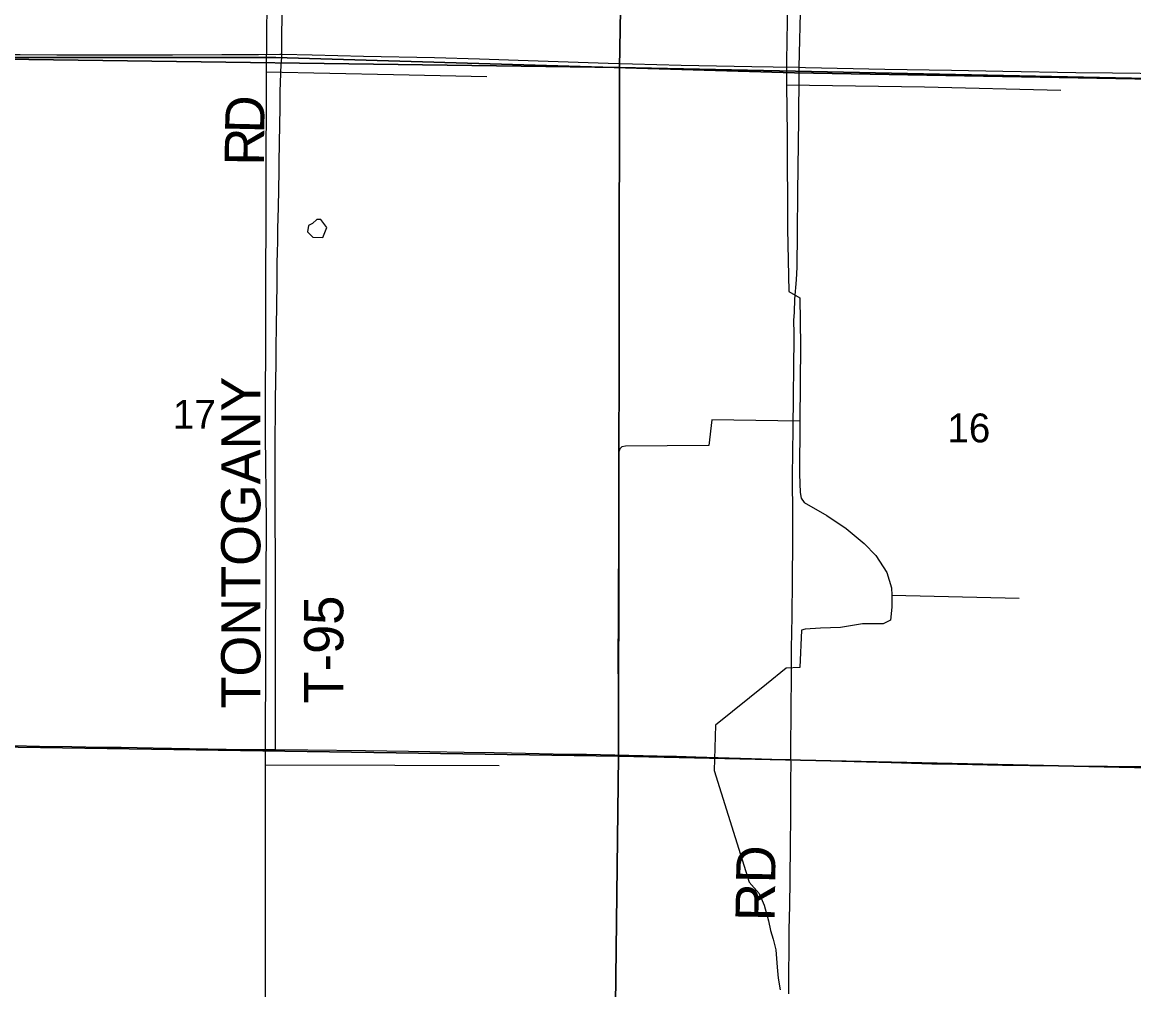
# Model space of a CAD drawing. Extents: x 1443599 to 1910620, y 1028088 to 1361369.
# Drawn here: x 1626749 to 1635252, y 1234297 to 1241703 of the extents above; entities that cross this region are included whole.
import ezdxf

# ---------------------------------------------------------------- set-up
doc = ezdxf.new("R2010")
doc.units = 0
for name, color, linetype in [('GM_X_County_Road', 7, 'Continuous'), ('GM_X_Minor_Lake', 7, 'Continuous'), ('GM_X_Minor_River', 7, 'Continuous'), ('GM_X_Section', 7, 'Continuous'), ('GM_X_Section_Text', 7, 'Continuous'), ('GM_X_Township', 7, 'Continuous'), ('GM_X_Township_Road', 7, 'Continuous'), ('GM_X_Township_Road_Text', 7, 'Continuous')]:
    doc.layers.add(name, color=color, linetype=linetype)

msp = doc.modelspace()

# ---------------------------------------------------------------- linework, layer by layer
at = {"layer": 'GM_X_County_Road'}
for points in [[(1626037.2, 1236177), (1626258.7, 1236174.2), (1626471.8, 1236168.4), (1626685.2, 1236165.4), (1626882, 1236160.5), (1627128.2, 1236159.1), (1627341.4, 1236154.7), (1627505.5, 1236152.6), (1627751.6, 1236148), (1628309.4, 1236138.6), (1628489.9, 1236137), (1628686.8, 1236136.1), (1628687.6, 1236136.1)], [(1628687.6, 1236136.1), (1628932.9, 1236132.6), (1629376, 1236127.4), (1629868.3, 1236120), (1630130.8, 1236115.7), (1630360.4, 1236111.8), (1630491.8, 1236109.7), (1630918.2, 1236101.1), (1631065.9, 1236100.8), (1631607.3, 1236088.4), (1631755, 1236085), (1631902.6, 1236080.5), (1632329.1, 1236067.6), (1632558.7, 1236060.6), (1632630, 1236058.6)], [(1632630, 1236058.6), (1632755.4, 1236054.5), (1633018, 1236047.5), (1633395.2, 1236036), (1633706.8, 1236026.5), (1633903.7, 1236023.2), (1634248.2, 1236016.1), (1634457.5, 1236013.4), (1634740.3, 1236009.9), (1635052.1, 1236007.6), (1635314.6, 1236004.7), (1635478.7, 1236003.7), (1635626.4, 1236002.7), (1635888.9, 1236000.7), (1636036.5, 1235999.5), (1636282.6, 1235997.2), (1636479.5, 1235994.7), (1636594.2, 1235991.8), (1636666.7, 1235993.1)]]:
    msp.add_lwpolyline(points, dxfattribs=at)
at = {"layer": 'GM_X_Minor_Lake'}
msp.add_line((1629002.2, 1240192.4), (1628969.6, 1240160.9), dxfattribs=at)
msp.add_lwpolyline([(1628969.6, 1240160.9), (1628939.2, 1240145.4), (1628930.3, 1240097.4), (1628971.6, 1240058.5), (1629047.7, 1240055.1), (1629079.2, 1240130.8), (1629034.3, 1240193.8), (1629002.2, 1240192.4)], dxfattribs=at)
at = {"layer": 'GM_X_Minor_River'}
for points in [[(1628622.4, 1242132.2), (1628615, 1241323.5), (1628610.9, 1239521.4), (1628608.3, 1238540), (1628615.7, 1237875.6), (1628610.8, 1236986.6), (1628606.5, 1236017.3), (1628607.8, 1234925.5), (1628607.9, 1233982.3)], [(1632606.4, 1242019.5), (1632596.7, 1241403.6), (1632595.3, 1241223), (1632600.1, 1240843.6), (1632602.4, 1240121), (1632613.4, 1239641.2), (1632696.6, 1239593.5), (1632701.7, 1239228.1), (1632696.7, 1238648.2), (1632695, 1238242.8), (1632700.4, 1238104.2), (1632707.5, 1238059.9), (1632731, 1238027.4), (1632905.3, 1237925.8), (1633051.6, 1237826.7), (1633189.7, 1237713.8), (1633280.1, 1237621.8), (1633363.8, 1237491.8), (1633399.6, 1237372.7), (1633402.5, 1237316.4), (1633400.8, 1237224.1), (1633390.9, 1237126), (1633336.3, 1237098.9), (1633178, 1237097.8), (1633009.2, 1237070.9), (1632856.9, 1237065.7), (1632738.6, 1237057.9), (1632710.4, 1237048.4), (1632696.9, 1236763.7), (1632592.7, 1236759.6), (1632442.1, 1236636), (1632051.6, 1236322.2), (1632043, 1235975.1), (1632309.2, 1235119.2), (1632385.7, 1235033.5), (1632424, 1234944.5), (1632457.8, 1234825.4), (1632474.4, 1234750.9), (1632493.2, 1234684.3), (1632513.7, 1234603.6), (1632525.2, 1234468.9), (1632531.6, 1234384.5), (1632545.9, 1234295.9)], [(1628615, 1241323.5), (1629588.2, 1241303.3), (1630303, 1241287.9)], [(1632595.3, 1241223), (1633650.7, 1241209.2), (1634693.8, 1241181.7)], [(1632696.7, 1238648.2), (1632023.8, 1238658.8), (1632002.1, 1238462.5), (1631365, 1238458.4), (1631334.8, 1238452.9), (1631320.5, 1238437.1), (1631309.9, 1238407.2), (1631312.4, 1238324.9), (1631305.9, 1236715.4)], [(1633402.5, 1237316.4), (1634375.6, 1237294.2)], [(1628606.5, 1236017.3), (1629600, 1236014.8), (1630397.2, 1236013.9)]]:
    msp.add_lwpolyline(points, dxfattribs=at)
at = {"layer": 'GM_X_Section'}
for points in [[(1626109.6, 1246727.6), (1631408.8, 1246654.1), (1631319.3, 1241355.1), (1626044.2, 1241426.2)], [(1631408.8, 1246654.1), (1636807.6, 1246539.3), (1636704.1, 1241244.4), (1631319.3, 1241355.1)], [(1626044.2, 1241426.2), (1631319.3, 1241355.1), (1631310.2, 1236085), (1626033.2, 1236164.2)], [(1631319.3, 1241355.1), (1636704.1, 1241244.4), (1636650.8, 1235966.8), (1631310.2, 1236085)], [(1626033.2, 1236164.2), (1631310.2, 1236085), (1631247.2, 1230796.7), (1626003.9, 1230849.2)], [(1631310.2, 1236085), (1636650.8, 1235966.8), (1636595.3, 1230648.8), (1631247.2, 1230796.7)]]:
    msp.add_lwpolyline(points, close=True, dxfattribs=at)
at = {"layer": 'GM_X_Township'}
for points in [[(1636706.1, 1241244.3), (1632655.7, 1241314.7), (1628687.8, 1241432.1), (1626059.6, 1241433.1), (1620678.1, 1241550.1), (1620639.2, 1236302.8), (1615310.1, 1236311.4)], [(1636476.6, 1220085.9), (1631101.7, 1220199.8), (1625906.6, 1220301), (1625693.5, 1220295.5), (1620438.7, 1220361.2), (1620464.9, 1220696.8), (1620510.4, 1225659.3), (1620565.2, 1230923), (1620593.8, 1233582.6), (1620639.2, 1236302.8), (1620678.1, 1241550.1), (1626059.6, 1241433.1), (1628687.8, 1241432.1), (1632655.7, 1241314.7), (1636706.1, 1241244.3)]]:
    msp.add_lwpolyline(points, dxfattribs=at)
at = {"layer": 'GM_X_Township_Road'}
for points in [[(1632693.3, 1241357.3), (1632705.5, 1241880.4), (1632713.9, 1242241.5), (1632721, 1242536.9), (1632725.9, 1242783.1), (1632744.7, 1243570.9), (1632752.4, 1243882.8), (1632751.3, 1243948.4), (1632747.7, 1243997.5), (1632741.1, 1244062.8), (1632738.4, 1244111.9), (1632738.1, 1244177.6), (1632752.2, 1244686.3), (1632762.3, 1245014.5), (1632775.3, 1245474), (1632800.7, 1246425.9), (1632804.9, 1246660.3)], [(1628735, 1241457.2), (1628735, 1241457.3), (1628735.1, 1241468.1), (1628735.5, 1241494.6), (1628735.5, 1241517.2), (1628735.8, 1241589.3), (1628738.4, 1241760)], [(1626069.5, 1241459.9), (1626339.6, 1241456.5), (1626503.7, 1241455.6), (1626733.6, 1241454.7), (1627012.7, 1241452.1), (1627505.2, 1241453), (1627899.2, 1241453.4), (1628276.8, 1241455.1), (1628457.4, 1241455.2), (1628555.9, 1241455.7), (1628720, 1241457.5), (1628735, 1241457.2)], [(1628686.1, 1236722.1), (1628686, 1236736.6), (1628686.2, 1236854.8), (1628685.9, 1236940.1), (1628685.6, 1237028.7), (1628685.6, 1237274.9), (1628685.5, 1237406.2), (1628685.7, 1237547.4), (1628685.9, 1237645.8), (1628685.1, 1237862.5), (1628685, 1238033.2), (1628684.5, 1238266.2), (1628685, 1238519), (1628686, 1238712.6), (1628687, 1238821), (1628689, 1238949), (1628691.3, 1239099.9), (1628692.6, 1239214.8), (1628694.6, 1239372.4), (1628698.3, 1239703.9), (1628700.3, 1239868), (1628701.8, 1239933.6), (1628703.4, 1240035.3), (1628705, 1240120.7), (1628708.9, 1240288), (1628713.5, 1240558.9), (1628714.4, 1240637.7), (1628716.3, 1240772.3), (1628719, 1240923.3), (1628721.4, 1241041.4), (1628723.3, 1241172.7), (1628726.7, 1241310.6), (1628729.9, 1241383), (1628732.1, 1241407.3), (1628733.8, 1241429.9), (1628734.7, 1241442.5), (1628735, 1241457.2)], [(1628735, 1241457.2), (1628966.3, 1241453.3), (1629360.1, 1241442.5), (1629901.8, 1241431.5), (1630246.4, 1241421.4), (1630541.8, 1241411.6), (1630771.5, 1241403.8), (1631230.9, 1241388.5), (1631789, 1241374.8), (1632330.6, 1241364.3), (1632494.7, 1241360.1), (1632693.3, 1241357.3)], [(1632630, 1236058.6), (1632629.1, 1236136.8), (1632630.6, 1236432.3), (1632633.6, 1236711.4), (1632634.5, 1236908.4), (1632638, 1237154.6), (1632642, 1237433.6), (1632643.6, 1237729.1), (1632644.9, 1237926), (1632642.1, 1238221.5), (1632643.6, 1238418.5), (1632646.5, 1238582.5), (1632649.6, 1238845.2), (1632652.2, 1239058.6), (1632652, 1239140.4), (1632653.8, 1239205.7), (1632653.3, 1239320.4), (1632652.9, 1239418.9), (1632655.7, 1239484.4), (1632660.3, 1239582.8), (1632672.4, 1239730.1), (1632676.7, 1239828.4), (1632680.4, 1240091.1), (1632682.8, 1240403), (1632689.6, 1240961.2), (1632692.1, 1241305.9), (1632693.3, 1241357.3)], [(1632693.3, 1241357.3), (1632741, 1241356.6), (1633348.3, 1241344.3), (1633857.1, 1241334.4), (1634251.1, 1241328.2), (1634809.2, 1241318.6), (1635088.3, 1241314.4), (1635301.7, 1241311.9), (1635547.9, 1241310), (1636122.5, 1241306.2), (1636516.5, 1241300.3), (1636697, 1241295.6), (1636731.1, 1241294.7)], [(1628687.6, 1236136.1), (1628687.4, 1236159), (1628687.1, 1236195), (1628685.9, 1236263.9), (1628685.2, 1236352.6), (1628685.3, 1236460.9), (1628686.3, 1236634.9), (1628686.1, 1236722.1)], [(1632613.8, 1234266.7), (1632614.2, 1234463.7), (1632615.6, 1234562.2), (1632617, 1234759.2), (1632620.7, 1234939.8), (1632623.5, 1235136.1), (1632627.2, 1235414.9), (1632629.5, 1235611.9), (1632628.5, 1235710.3), (1632629.6, 1235890.9), (1632630.2, 1236038.4), (1632630, 1236058.6)]]:
    msp.add_lwpolyline(points, dxfattribs=at)

# ---------------------------------------------------------------- texts
at = {"layer": 'GM_X_Section_Text'}
for s, p in [('17', (1627901.3, 1238590.8)), ('16', (1633825.9, 1238486.8))]:
    msp.add_text(s, height=221, rotation=0.00001, dxfattribs=at).set_placement(p)
at = {"layer": 'GM_X_Township_Road_Text'}
for s, rotation, p in [('D', 88.73222, (1628599.8, 1240849.5)), ('R', 89.41452, (1628597.3, 1240604.1)), ('TONTOGANY', 90, (1628570.8, 1236449.3)), ('T-95', 90, (1629205.2, 1236488.9)), ('RD', 89.03021, (1632504.5, 1234820))]:
    msp.add_text(s, height=300, rotation=rotation, dxfattribs=at).set_placement(p)

doc.saveas('drawing.dxf')
